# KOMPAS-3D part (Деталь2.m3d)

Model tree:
1. Эскиз:1
2. Операция выдавливания:1
     Расстояние 1 = 25; Расстояние 2 = 60
3. Эскиз:2
4. Эскиз:3
5. Операция выдавливания:2
     Расстояние 1 = 45; Расстояние 2 = 60
6. Эскиз:4
7. Операция выдавливания:3
     Расстояние 1 = 65; Расстояние 2 = 60
8. Эскиз:5
9. Вырезать элемент выдавливания:1
     Расстояние 1 = 35
10. Эскиз:6
11. Вырезать элемент выдавливания:2
     Расстояние 1 = 15
12. Эскиз:7
13. Вырезать элемент выдавливания:3
     Расстояние 1 = 15
14. Эскиз:8
15. Вырезать элемент выдавливания:4
     Расстояние 1 = 15
16. Эскиз:10
17. Эскиз:11
18. Вырезать элемент выдавливания:5
     Расстояние 1 = 15
19. Эскиз:12
20. Вырезать элемент выдавливания:6
     Расстояние 1 = 15
21. Эскиз:13
